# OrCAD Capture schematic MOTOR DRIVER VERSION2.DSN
size A
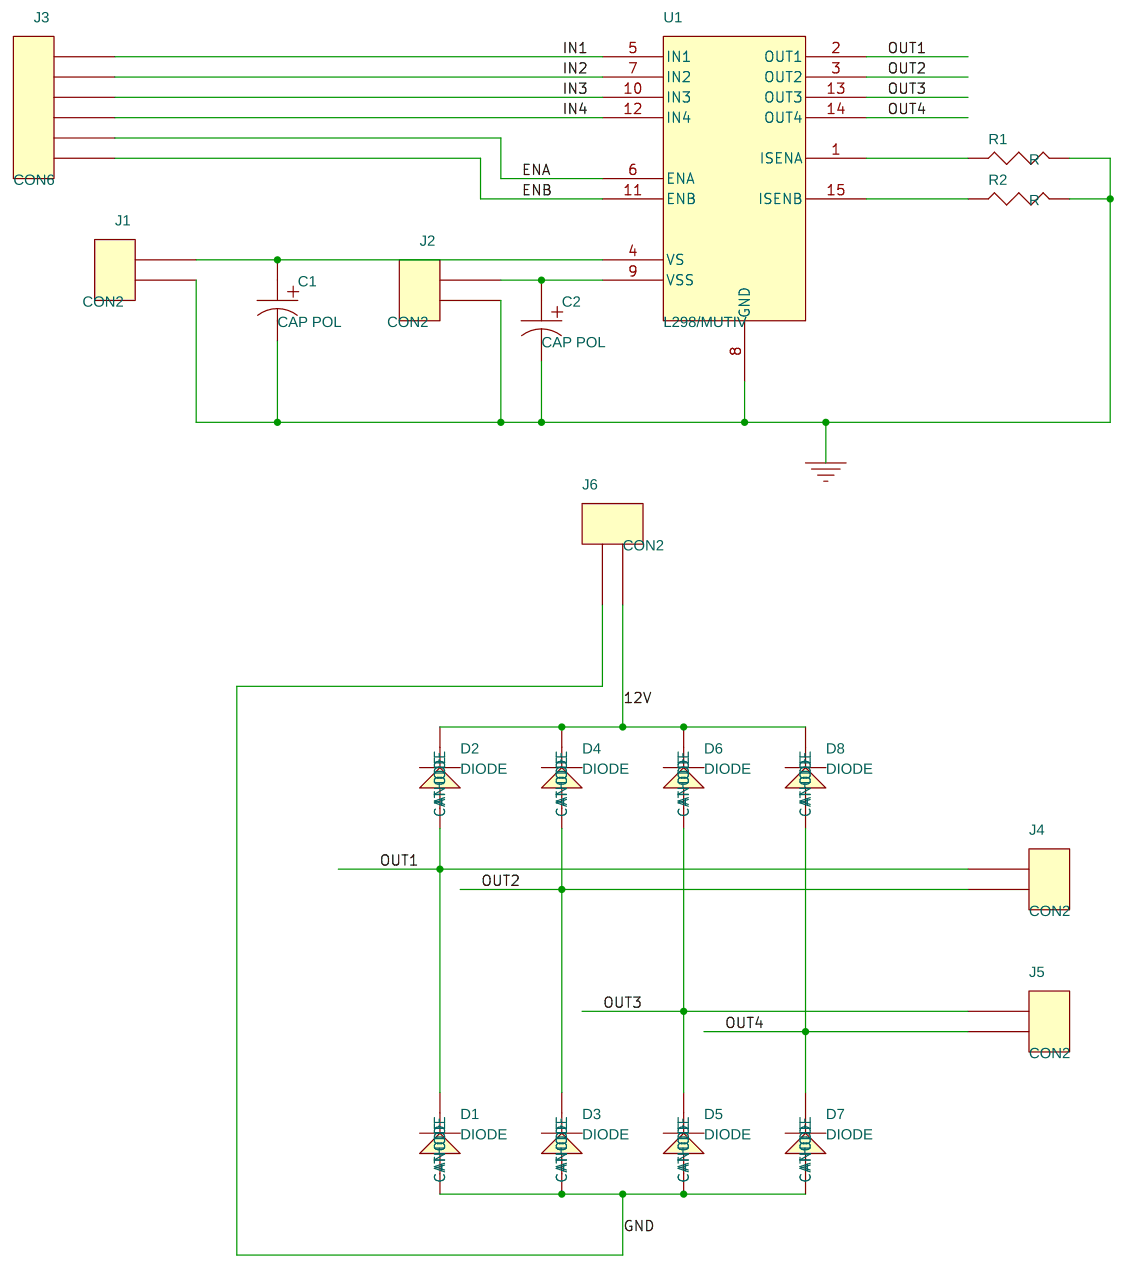
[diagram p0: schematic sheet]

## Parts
C1  CAP POL  [GU-CAPCYL200]
C2  CAP POL  [GU-CAPCYL200]
D1  DIODE  [GU-1N4001]
D2  DIODE  [GU-1N4001]
D3  DIODE  [GU-1N4001]
D4  DIODE  [GU-1N4001]
D5  DIODE  [GU-1N4001]
D6  DIODE  [GU-1N4001]
D7  DIODE  [GU-1N4001]
D8  DIODE  [GU-1N4001]
J1  CON2  [GU-MOLEX2]
J2  CON2  [GU-MOLEX2]
J3  CON6  [GU-MOLEX6]
J4  CON2  [GU-MOLEX2]
J5  CON2  [GU-MOLEX2]
J6  CON2  [GU-MOLEX2]
R1  R  [GU-RC400]
R2  R  [GU-RC400]
U1  L298/MUTIV  [GU-L298-HSINK2]

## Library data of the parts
C1 C2 = CAP_POL
D1-D8 = DIODE
J1 J2 J4-J6 = CON2
J3 = CON6
R1 R2 = R
U1 = L298_MUTIV_2

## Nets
12V: D2.2(CATHODE) D4.2(CATHODE) D6.2(CATHODE) D8.2(CATHODE) J6.2
GND: C1.2 C2.2 D1.1(ANODE) D3.1(ANODE) D5.1(ANODE) D7.1(ANODE) J1.2 J2.2 J6.1 R1.2 R2.2 U1.8(GND)
ENA: J3.5 U1.6(ENA)
ENB: J3.6 U1.11(ENB)
IN1: J3.1 U1.5(IN1)
IN2: J3.2 U1.7(IN2)
IN3: J3.3 U1.10(IN3)
IN4: J3.4 U1.12(IN4)
OUT1: D1.2(CATHODE) D2.1(ANODE) J4.1 U1.2(OUT1)
OUT2: D3.2(CATHODE) D4.1(ANODE) J4.2 U1.3(OUT2)
OUT3: D5.2(CATHODE) D6.1(ANODE) J5.1 U1.13(OUT3)
OUT4: D7.2(CATHODE) D8.1(ANODE) J5.2 U1.14(OUT4)
N01235: R2.1 U1.15(ISENB)
N01241: R1.1 U1.1(ISENA)
N01245: C1.1 J1.1 U1.4(VS)
N01267: C2.1 J2.1 U1.9(VSS)
